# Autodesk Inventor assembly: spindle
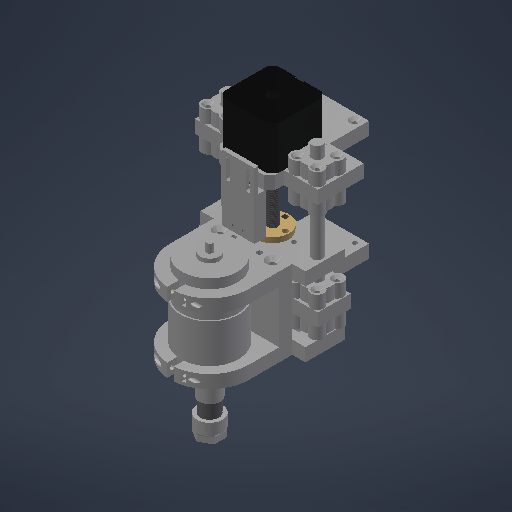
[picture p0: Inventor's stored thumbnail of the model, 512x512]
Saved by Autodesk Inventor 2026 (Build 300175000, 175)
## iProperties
Created: 2025-04
Part Number: spindle
Material: Generisch
Document SubType Name: Assembly
Designer: BennF
Author: BennF
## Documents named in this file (16)
- C:\Users\BennF\Nextcloud\Benedikt\FabAcademy\week12\CAD\z-axis\z-axis.iam
- C:\Users\BennF\Nextcloud\Benedikt\FabAcademy\week12\CAD\z-axis\spindel.ipt
- C:\Users\BennF\Nextcloud\Benedikt\FabAcademy\week12\CAD\z-axis\z_axis_spindel_backplate.ipt
- C:\Users\BennF\Nextcloud\Benedikt\FabAcademy\week12\CAD\z-axis\z_axis_spindel_top_plate.ipt
- C:\Users\BennF\Nextcloud\Benedikt\FabAcademy\week12\CAD\z-axis\z_axis_spindel_bottom_plate.ipt
- C:\Users\BennF\Nextcloud\Benedikt\FabAcademy\week12\CAD\z-axis\z_axis_8mm_rod.ipt
- C:\Users\BennF\Nextcloud\Benedikt\FabAcademy\week12\CAD\z-axis\z_axis_mounting_plate_stepper.ipt
- C:\Users\BennF\Nextcloud\Benedikt\FabAcademy\week12\CAD\z-axis\stepper_Motor.ipt
- C:\Users\BennF\Nextcloud\Benedikt\FabAcademy\week12\CAD\z-axis\z_axis_mounting_plate.ipt
- C:\Users\BennF\Nextcloud\Benedikt\FabAcademy\week12\CAD\LM8UU.ipt
- C:\Users\BennF\Nextcloud\Benedikt\FabAcademy\week12\CAD\z-axis\z_axis_LM8UU_cap_bottom.ipt
- C:\Users\BennF\Nextcloud\Benedikt\FabAcademy\week12\CAD\z-axis\z_axis_LM8UU_cap_top.ipt
- C:\Users\BennF\Nextcloud\Benedikt\FabAcademy\week12\CAD\z-axis\z_axis_spacer.ipt
- C:\Users\BennF\Nextcloud\Benedikt\FabAcademy\week12\CAD\t8_screw_nut_polymere.ipt
- C:\Users\BennF\Nextcloud\Benedikt\FabAcademy\week12\CAD\z-axis\end_switch_holder_z.ipt
- C:\Users\BennF\Nextcloud\Benedikt\FabAcademy\week12\CAD\end_switch_moc.ipt
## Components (26 placed, 15 different names)
1. spindel:1 — Insert:2
2. z_axis_spindel_backplate:1 — Insert:1, Insert:3, Insert:4, Insert:5, Angle:1
3. z_axis_spindel_top_plate:1 — Insert:4, Insert:5, Insert:26, Insert:27
4. z_axis_spindel_bottom_plate:1 — Insert:2, Insert:1, Insert:3, Insert:8, Insert:9
5. z_axis_8mm_rod:1 — Insert:8, Cylindrical:1
6. z_axis_8mm_rod:2 — Insert:9
7. z_axis_mounting_plate_stepper:1
8. stepper_Motor:1 — Insert:6, Insert:7
9. z_axis_mounting_plate:1
10. LM8UU:1 — Insert:25
11. LM8UU:2 — Insert:19
12. LM8UU:3 — Insert:24
13. LM8UU:4 — Insert:16, Cylindrical:1
14. z_axis_LM8UU_cap_top:1 — Insert:13, Insert:16
15. z_axis_LM8UU_cap_top:2 — Insert:17, Insert:19
16. z_axis_LM8UU_cap_top:3 — Insert:20, Insert:24
17. z_axis_LM8UU_cap_top:4 — Insert:22, Insert:25
18. z_axis_LM8UU_cap_bottom:1 — Insert:12, Insert:15
19. z_axis_LM8UU_cap_bottom:2 — Insert:18
20. z_axis_LM8UU_cap_bottom:3 — Insert:21
21. z_axis_LM8UU_cap_bottom:4 — Insert:23
22. z_axis_spacer:1 — Insert:26, Insert:28, Insert:37
23. t8_screw_nut_polymere:1 — Insert:27
24. t8_screw_nut_polymere:2 — Insert:28, Insert:37
25. end_switch_holder_z:1 — Insert:35, Insert:36, Mate:2, Mate:3, Flush:3
26. end_switch_moc:1 — Insert:35, Insert:36
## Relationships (33: Insert 28, Mate 2, CylindricalJoint 1, Angle 1, Flush 1)
- Insert:1: z_axis_spindel_backplate:1 ↔ z_axis_spindel_bottom_plate:1
- Insert:2: spindel:1 ↔ z_axis_spindel_bottom_plate:1
- Insert:3: z_axis_spindel_backplate:1 ↔ z_axis_spindel_bottom_plate:1
- Insert:4: z_axis_spindel_backplate:1 ↔ z_axis_spindel_top_plate:1
- Insert:5: z_axis_spindel_backplate:1 ↔ z_axis_spindel_top_plate:1
- Insert:6: stepper_Motor:1
- Insert:7: stepper_Motor:1
- Insert:8: z_axis_spindel_bottom_plate:1 ↔ z_axis_8mm_rod:1
- Insert:9: z_axis_spindel_bottom_plate:1 ↔ z_axis_8mm_rod:2
- Insert:12: z_axis_LM8UU_cap_bottom:1
- Insert:13: z_axis_LM8UU_cap_top:1
- Insert:15: z_axis_LM8UU_cap_bottom:1
- Insert:16: LM8UU:4 ↔ z_axis_LM8UU_cap_top:1
- Insert:17: z_axis_LM8UU_cap_top:2
- Insert:18: z_axis_LM8UU_cap_bottom:2
- Insert:19: LM8UU:2 ↔ z_axis_LM8UU_cap_top:2
- Insert:20: z_axis_LM8UU_cap_top:3
- Insert:21: z_axis_LM8UU_cap_bottom:3
- Insert:22: z_axis_LM8UU_cap_top:4
- Insert:23: z_axis_LM8UU_cap_bottom:4
- Insert:24: LM8UU:3 ↔ z_axis_LM8UU_cap_top:3
- Insert:25: LM8UU:1 ↔ z_axis_LM8UU_cap_top:4
- Cylindrical:1: z_axis_8mm_rod:1 ↔ LM8UU:4
- Angle:1: z_axis_spindel_backplate:1
- Insert:26: z_axis_spindel_top_plate:1 ↔ z_axis_spacer:1
- Insert:27: z_axis_spindel_top_plate:1 ↔ t8_screw_nut_polymere:1
- Insert:28: z_axis_spacer:1 ↔ t8_screw_nut_polymere:2
- Insert:35: end_switch_holder_z:1 ↔ end_switch_moc:1
- Insert:36: end_switch_holder_z:1 ↔ end_switch_moc:1
- Mate:2: end_switch_holder_z:1
- Mate:3: end_switch_holder_z:1
- Flush:3: end_switch_holder_z:1
- Insert:37: z_axis_spacer:1 ↔ t8_screw_nut_polymere:2
